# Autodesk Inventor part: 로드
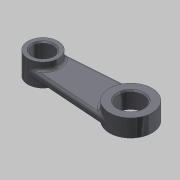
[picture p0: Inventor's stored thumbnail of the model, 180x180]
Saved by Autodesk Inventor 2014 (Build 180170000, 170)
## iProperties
Created: 2015-10
Part Number: 로드
Document SubType Name: Modeling
Designer: mdu
Density: 7.86 g/cm^3
Material: 강철, 연강
Mass: 20.3759 g
Surface Area: 22.2266 cm^2
Volume: 2.59236 cm^3
Appearance: 강철 - 광택
Author: mdu
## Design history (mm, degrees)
sketch "스케치1"
  geometry: L1 (13.821, 5.985)-(48.643, 8.478); L2 (48.643, -8.478)-(13.821, -5.985); C1 r 4 at (14.25, 0) reference; A1 r 6 centre (14.25, 0) between (13.821, 5.985) and (13.821, -5.985); A2 r 8.5 centre (49.25, 0) between (48.643, 8.478) and (48.643, -8.478); 1 further point
  constraints: 4 end point, 4 point on circle, 4 tangent, 2 centre point, 1 coincident, 1 horizontal alignment
  dimensions: "d0" = 12 diameter of A1; "d1" = 35 distance of A2.centre A1.centre; "d2" = 17 diameter of A2
  node "참조1"
extrude "돌출1" new body sketch "스케치1" distance "d3" = 9; taper "d4" = 0 deg
node "작업 평면1"
node "작업 평면2"
extrude "돌출2" join sketch "스케치1" stored distance "d7" = 10; taper "d8" = 0 deg
node "작업 평면3"
extrude "돌출3" join sketch "스케치1" stored distance "d10" = 10; taper "d11" = 0 deg
hole "구멍1" diameter "d14" = 10; stored, may be unused: countersink angle "d18" = 90 deg, drill point angle "d20" = 118 deg; dims "d12" = 10, "d13" = 10, "d15" = 6, "d16" = 4, "d17" = 2, "d19" = 8
fillet "모깎기1" dims "d21" = 1
chamfer "모따기1" distance "d22" = 0.5; stored, may be unused: second distance "d23" = 2, angle "d24" = 45 deg
chamfer "모따기2" distance "d25" = 0.5; stored, may be unused: second distance "d26" = 2, angle "d27" = 45 deg
node "솔리드1"
other parameters: "d5" = -6, "d6" = -3, "d9" = -4
